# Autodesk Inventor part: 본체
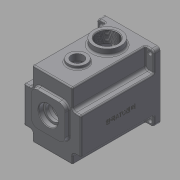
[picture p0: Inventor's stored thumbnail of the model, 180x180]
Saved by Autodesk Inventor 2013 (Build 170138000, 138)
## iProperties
Created: 2016-02
Part Number: 본체
Material: 일반
Document SubType Name: Modeling
Designer: mduedu
Density: 2.71 g/cm^3
Author: mduedu
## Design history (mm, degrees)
sketch "스케치1"
  geometry: L1 (-47, -47)-(47, -47); L2 (47, -47)-(47, 63); L3 (47, 63)-(-47, 63); L4 (-47, 63)-(-47, -47); 2 further points
  constraints: 8 end point, 2 parallel, 1 horizontal, 1 midpoint, 1 perpendicular, 1 vertical alignment
  dimensions: "d0" = 94 distance of L2.end L3.end; "d155" = 110 distance of L1.end L2.end; "d156" = 47 distance from line of L1 point (0, 0)
extrude "돌출1" new body sketch "스케치1" distance "d2" = 130; taper "d3" = 0 deg
sketch "스케치3"
  geometry: C1 r 40 at (0, 0); 1 further point
  constraints: 1 centre point, 1 coincident
  dimensions: "d9" = 80 diameter of C1
extrude "돌출3" cut sketch "스케치3" distance "d11" = 121; taper "d12" = 0 deg
sketch "스케치4"
  geometry: C1 r 21 at (0, 11); 1 further point
  constraints: 1 centre point, 1 vertical alignment
  dimensions: "d13" = 21 radius of C1; "d15" = 11 distance of point (0, 0) C1.centre
extrude "돌출4" join sketch "스케치4" distance "d16" = 7; taper "d17" = 0 deg
sketch "스케치5"
  geometry: C1 r 15 at (0, -20); 1 further point
  constraints: 1 centre point, 1 vertical alignment
  dimensions: "d18" = 15 radius of C1; "d20" = 20 distance of point (0, 0) C1.centre
extrude "돌출5" join sketch "스케치5" distance "d21" = 7; taper "d22" = 0 deg
sketch "스케치6"
  geometry: L1 (-28, -17)-(28, -17); L2 (28, -17)-(28, 39); L3 (28, 39)-(-28, 39); L4 (-28, 39)-(-28, -17); L5 (-28, -17)-(28, 39); L6 (28, -17)-(-28, 39); C1 r 28 at (0, 11); A1 r 21 centre (0, 11) between (8.978, -7.984) and (-8.978, -7.984) reference; 1 further point
  constraints: 12 end point, 2 midpoint, 2 parallel, 2 tangent, 1 centre point, 1 coincident, 1 horizontal, 1 perpendicular
  dimensions: "d23" = 56 diameter of C1
extrude "돌출6" join sketch "스케치6" distance "d25" = 7; taper "d26" = -3 deg
hole "구멍1" diameter "d29" = 35; stored, may be unused: countersink angle "d33" = 90 deg, drill point angle "d35" = 0 deg; dims "d27" = 10, "d28" = 10, "d30" = 6, "d31" = 4, "d32" = 2, "d34" = 10
hole "구멍2" diameter "d38" = 22; stored, may be unused: countersink angle "d42" = 90 deg, drill point angle "d44" = 0 deg; dims "d36" = 10, "d37" = 10, "d39" = 6, "d40" = 4, "d41" = 2, "d43" = 7
hole "구멍3" diameter "d47" = 19; stored, may be unused: countersink angle "d51" = 90 deg, drill point angle "d53" = 0 deg; dims "d45" = 10, "d46" = 10, "d48" = 6, "d49" = 4, "d50" = 2, "d52" = 1
hole "구멍4" diameter "d56" = 32; stored, may be unused: countersink angle "d60" = 90 deg, drill point angle "d62" = 0 deg; dims "d57" = 6, "d58" = 4, "d59" = 2, "d61" = 8, "d220" = 10, "d221" = 10
hole "구멍5" diameter "d65" = 25; stored, may be unused: countersink angle "d69" = 90 deg, drill point angle "d71" = 0 deg; dims "d63" = 10, "d64" = 10, "d66" = 6, "d67" = 4, "d68" = 2, "d70" = 8
fillet "모깎기2" dims "d73" = 0.3
fillet "모깎기3" dims "d74" = 2
chamfer "모따기1" distance "d75" = 1; stored, may be unused: second distance "d76" = 2, angle "d77" = 45 deg
fillet "모깎기4" dims "d78" = 3
sketch "스케치16"
  geometry: L1 (-23, 32.726)-(23, 32.726); L2 (23, 32.726)-(23, 53); L3 (23, 53)-(-23, 53); L4 (-23, 53)-(-23, 32.726); L5 (-47, 63)-(47, 63) reference; 3 further points
  constraints: 8 end point, 2 parallel, 1 horizontal, 1 midpoint, 1 perpendicular, 1 vertical alignment, 2 other
  dimensions: "d160" = 46 distance of L2.end L3.end; "d163" = 10 distance between parallel lines of L3 L5
extrude "돌출15" cut sketch "스케치16" stored distance "d164" = 10; taper "d165" = 0 deg
fillet "모깎기5" dims "d79" = 2
fillet "모깎기15" dims "d166" = 5
sketch "스케치7"
  geometry: L1 (-23, 48)-(-23, 35.228) reference; L2 (23, 35.228)-(23, 48) reference; L3 (18, 53)-(-18, 53) reference; L4 (47, 63)-(47, -47) reference; L5 (47, -47)-(-47, -47) reference; L6 (-47, -47)-(-47, 63) reference; L7 (-47, 63)-(47, 63) reference; L8 (-26, 48)-(-26, 35.228); L9 (26, 35.228)-(26, 48); L10 (18, 56)-(-18, 56); C1 r 43 at (0, 0); A1 r 5 centre (-18, 48) between (-18, 53) and (-23, 48) reference; A2 r 5 centre (-28, 35.228) between (-24.889, 31.314) and (-23, 35.228) reference; A3 r 40 centre (0, 0) between (-24.889, 31.314) and (24.889, 31.314) reference; A4 r 5 centre (28, 35.228) between (23, 35.228) and (24.889, 31.314) reference; A5 r 5 centre (18, 48) between (23, 48) and (18, 53) reference; A6 r 8 centre (-18, 48) between (-18, 56) and (-26, 48); A7 r 2 centre (-28, 35.228) between (-26.756, 33.662) and (-26, 35.228); A8 r 43 centre (0, 0) between (-26.756, 33.662) and (26.756, 33.662); A9 r 2 centre (28, 35.228) between (26, 35.228) and (26.756, 33.662); A10 r 8 centre (18, 48) between (26, 48) and (18, 56); 1 further point
  constraints: 10 point on circle, 6 centre point, 6 end point, 1 coincident, 7 other
  dimensions: "d80" = 86 diameter of C1; "d167" = 3 distance between parallel lines of L3 L10
extrude "돌출7" cut sketch "스케치7" distance "d83" = 9; taper "d84" = 0 deg
sketch "스케치8" dims "d168" = 36
  geometry: L1 (-36, 4)-(-39.799, 4); L2 (-36, -4)-(-39.799, -4); A1 r 4 centre (-36, 0) between (-36, 4) and (-36, -4); A2 r 40 centre (0, 0) between (-24.889, 31.314) and (24.889, 31.314) reference; A3 r 40 centre (0, 0) between (-39.799, 4) and (-39.799, -4); 2 further points
  constraints: 5 point on circle, 4 end point, 2 centre point, 2 coincident, 2 horizontal alignment, 2 tangent, 1 horizontal, 1 parallel, 2 other
  dimensions: "d169" = 4 radius of A1
extrude "돌출9" join sketch "스케치8" stored distance "d89" = 9; taper "d90" = 0 deg
fillet "모깎기6" dims "d91" = 3.5
node "작업 평면1"
sketch "스케치9"
  geometry: L1 (47, 63)-(33, 63); L2 (33, 63)-(33, 30); L3 (33, 30)-(47, 30); L4 (47, 30)-(47, 63); L5 (47, 63)-(-47, 63) reference; L6 (47, -47)-(47, 63) reference; A1 r 40 centre (0, 0) between (-39.148, -8.214) and (39.148, -8.214) reference; 1 further point
  constraints: 8 end point, 2 parallel, 1 coincident, 1 horizontal, 1 perpendicular
  dimensions: "d95" = 33 distance from line of L2 point (0, 0); "d96" = 30 distance from line of L3 point (0, 0)
extrude "돌출10" cut sketch "스케치9" distance "d97" = 110; taper "d98" = 0 deg
extrude "돌출21" cut sketch "스케치9" stored distance "d217" = 10; taper "d218" = 0 deg
sketch "스케치11" dims "d20" = 20
  geometry: L1 (-40, -40)-(40, -40); L2 (40, -40)-(40, 56); L3 (40, 56)-(-40, 56); L4 (-40, 56)-(-40, -40); L5 (-47, -47)-(47, -47) reference; L6 (47, 63)-(-47, 63) reference; L7 (-47, 63)-(-47, -47) reference; C1 r 3.5 at (-40, 56); C2 r 3.5 at (40, 56); C3 r 3.5 at (40, -40); C4 r 3.5 at (-40, -40); 1 further point
  constraints: 8 end point, 4 centre point, 4 coincident, 3 equal radius, 2 parallel, 1 horizontal, 1 perpendicular
  dimensions: "d109" = 80 distance of L2.end L3.end; "d112" = 7 diameter of C1; "d157" = 7 distance from line of L1.start L5; "d158" = 7 distance between parallel lines of L6 L3; "d159" = 7 distance from line of L7 L3.end
extrude "돌출12" cut sketch "스케치11" stored distance "d113" = 63; taper "d114" = 0 deg
fillet "모깎기7" dims "d115" = 5, "d187" = 5
fillet "모깎기8" dims "d116" = 5
fillet "모깎기18" dims "d219" = 2
fillet "모깎기12" dims "d120" = 2
fillet "모깎기13" dims "d121" = 2
sketch "스케치12"
  geometry: 3 further points
  constraints: 2 horizontal alignment
hole "구멍6" sketch "스케치12" at (36, 0), (-36, 0) diameter "d122" = 3.242; stored, may be unused: countersink angle "d126" = 90 deg, drill point angle "d128" = 120 deg; dims "d123" = 7, "d124" = 4, "d125" = 2, "d127" = 9
fillet "모깎기14" dims "d147" = 10
chamfer "모따기4" distance "d151" = 1; stored, may be unused: second distance "d152" = 2, angle "d153" = 45 deg
sketch "스케치20"
  geometry: L1 (73, -12)-(73, -130) reference; L2 (84, -8)-(77, -8) reference; L3 (84, 0)-(84, -8) reference; L4 (84, 0)-(0, 0) reference; L5 (7, -8)-(0, -8) reference; L6 (11, -130)-(11, -12) reference; L7 (0, -8)-(0, 0) reference; L8 (73, -130)-(11, -130) reference; L9 (42, 0)-(42, -130); C1 r 10 at (42, -89); A1 r 4 centre (77, -12) between (77, -8) and (73, -12) reference; A2 r 4 centre (7, -12) between (11, -12) and (7, -8) reference
  constraints: 2 end point, 1 centre point, 1 midpoint, 1 point on line
  dimensions: "d189" = 20 diameter of C1; "d190" = 41 distance from line of C1.centre L8
extrude "돌출19" cut sketch "스케치20" stored distance "d191" = 10; taper "d192" = 0 deg
sketch "스케치18"
  geometry: C1 r 15 at (42, -89); C2 r 10 at (42, -89) reference; 1 further point
  constraints: 1 centre point, 1 concentric
  dimensions: "d174" = 30 diameter of C1
extrude "돌출17" join sketch "스케치18" distance "d175" = 5; taper "d176" = 0 deg
fillet "모깎기16" dims "d177" = 2
sketch "스케치19"
  geometry: C1 r 10 at (18, 80) reference; C2 r 15 at (18, 80); 1 further point
  constraints: 1 centre point, 1 coincident
  dimensions: "d178" = 30 diameter of C2
extrude "돌출18" cut sketch "스케치19" distance "d181" = 5; taper "d182" = 0 deg
chamfer "모따기5" distance "d183" = 0.5; stored, may be unused: second distance "d184" = 2, angle "d185" = 45 deg
sketch "스케치21"
  geometry: L1 (-12, 14)-(-130, 14) reference; L2 (-8, 0)-(-8, 10) reference; L3 (0, 0)-(0, 100) reference; L4 (-8, 100)-(0, 100) reference; L5 (-8, 74)-(-8, 100) reference; L6 (-130, 70)-(-12, 70) reference; L7 (-130, 14)-(-130, 70) reference; L8 (0, 0)-(-8, 0) reference; L9 (-130, 14)-(-130, 70) reference; L10 (27.4, 42)-(-164.4, 42) reference; A1 r 4 centre (-12, 74) between (-12, 70) and (-8, 74) reference; A2 r 4 centre (-12, 10) between (-8, 10) and (-12, 14) reference; 3 further points
  constraints: 1 coincident, 1 point on line, 1 other
  dimensions: "d222" = 65 distance from line of point (-65, 42) L9
feature "엠보싱2" sketch "스케치21" dims "d20" = 20, "d193" = 0.5, "d194" = 0
sketch "스케치22"
  geometry: L1 (73, -12)-(73, -130) reference; L2 (84, -8)-(77, -8) reference; L3 (84, 0)-(84, -8) reference; L4 (84, 0)-(0, 0) reference; L5 (7, -8)-(0, -8) reference; L6 (11, -130)-(11, -12) reference; L7 (0, -8)-(0, 0) reference; L8 (73, -130)-(11, -130) reference; L9 (42, -130)-(42, 0); C1 r 17 at (42, -89) reference; C2 r 22.5 at (42, -40); A1 r 4 centre (77, -12) between (77, -8) and (73, -12) reference; A2 r 4 centre (7, -12) between (11, -12) and (7, -8) reference
  constraints: 2 end point, 1 centre point, 1 midpoint, 1 point on line
  dimensions: "d195" = 45 diameter of C2; "d197" = 40 distance from line of C2.centre L4
extrude "돌출20" join sketch "스케치22" distance "d198" = 10; taper "d199" = 0 deg
fillet "모깎기17" dims "d200" = 3
hole "구멍7" diameter "d203" = 33.376; stored, may be unused: countersink angle "d207" = 90 deg, drill point angle "d209" = 118 deg; dims "d204" = 6, "d205" = 4, "d206" = 2, "d208" = 8, "d223" = 10, "d224" = 10
chamfer "모따기6" distance "d210" = 1; stored, may be unused: second distance "d211" = 2, angle "d212" = 45 deg
fillet "모깎기19" dims "d225" = 2
node "솔리드1"
pattern_circular "원형 패턴1" dims angle "d93" = 360 deg
mirror "대칭1"
mirror "대칭2"
node "투영된 루프1"
node "투영된 루프2"
node "투영된 루프3"
node "절단 모서리 투영3"
